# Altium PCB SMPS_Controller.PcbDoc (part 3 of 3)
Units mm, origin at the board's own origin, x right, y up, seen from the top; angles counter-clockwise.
Board outline 157 x 106 mm, 2 copper layers (Top Layer, Bottom Layer); 245 components, 175 nets, 948 pads, 171 vias.
Unrouted connection lines stored in the file: 2.
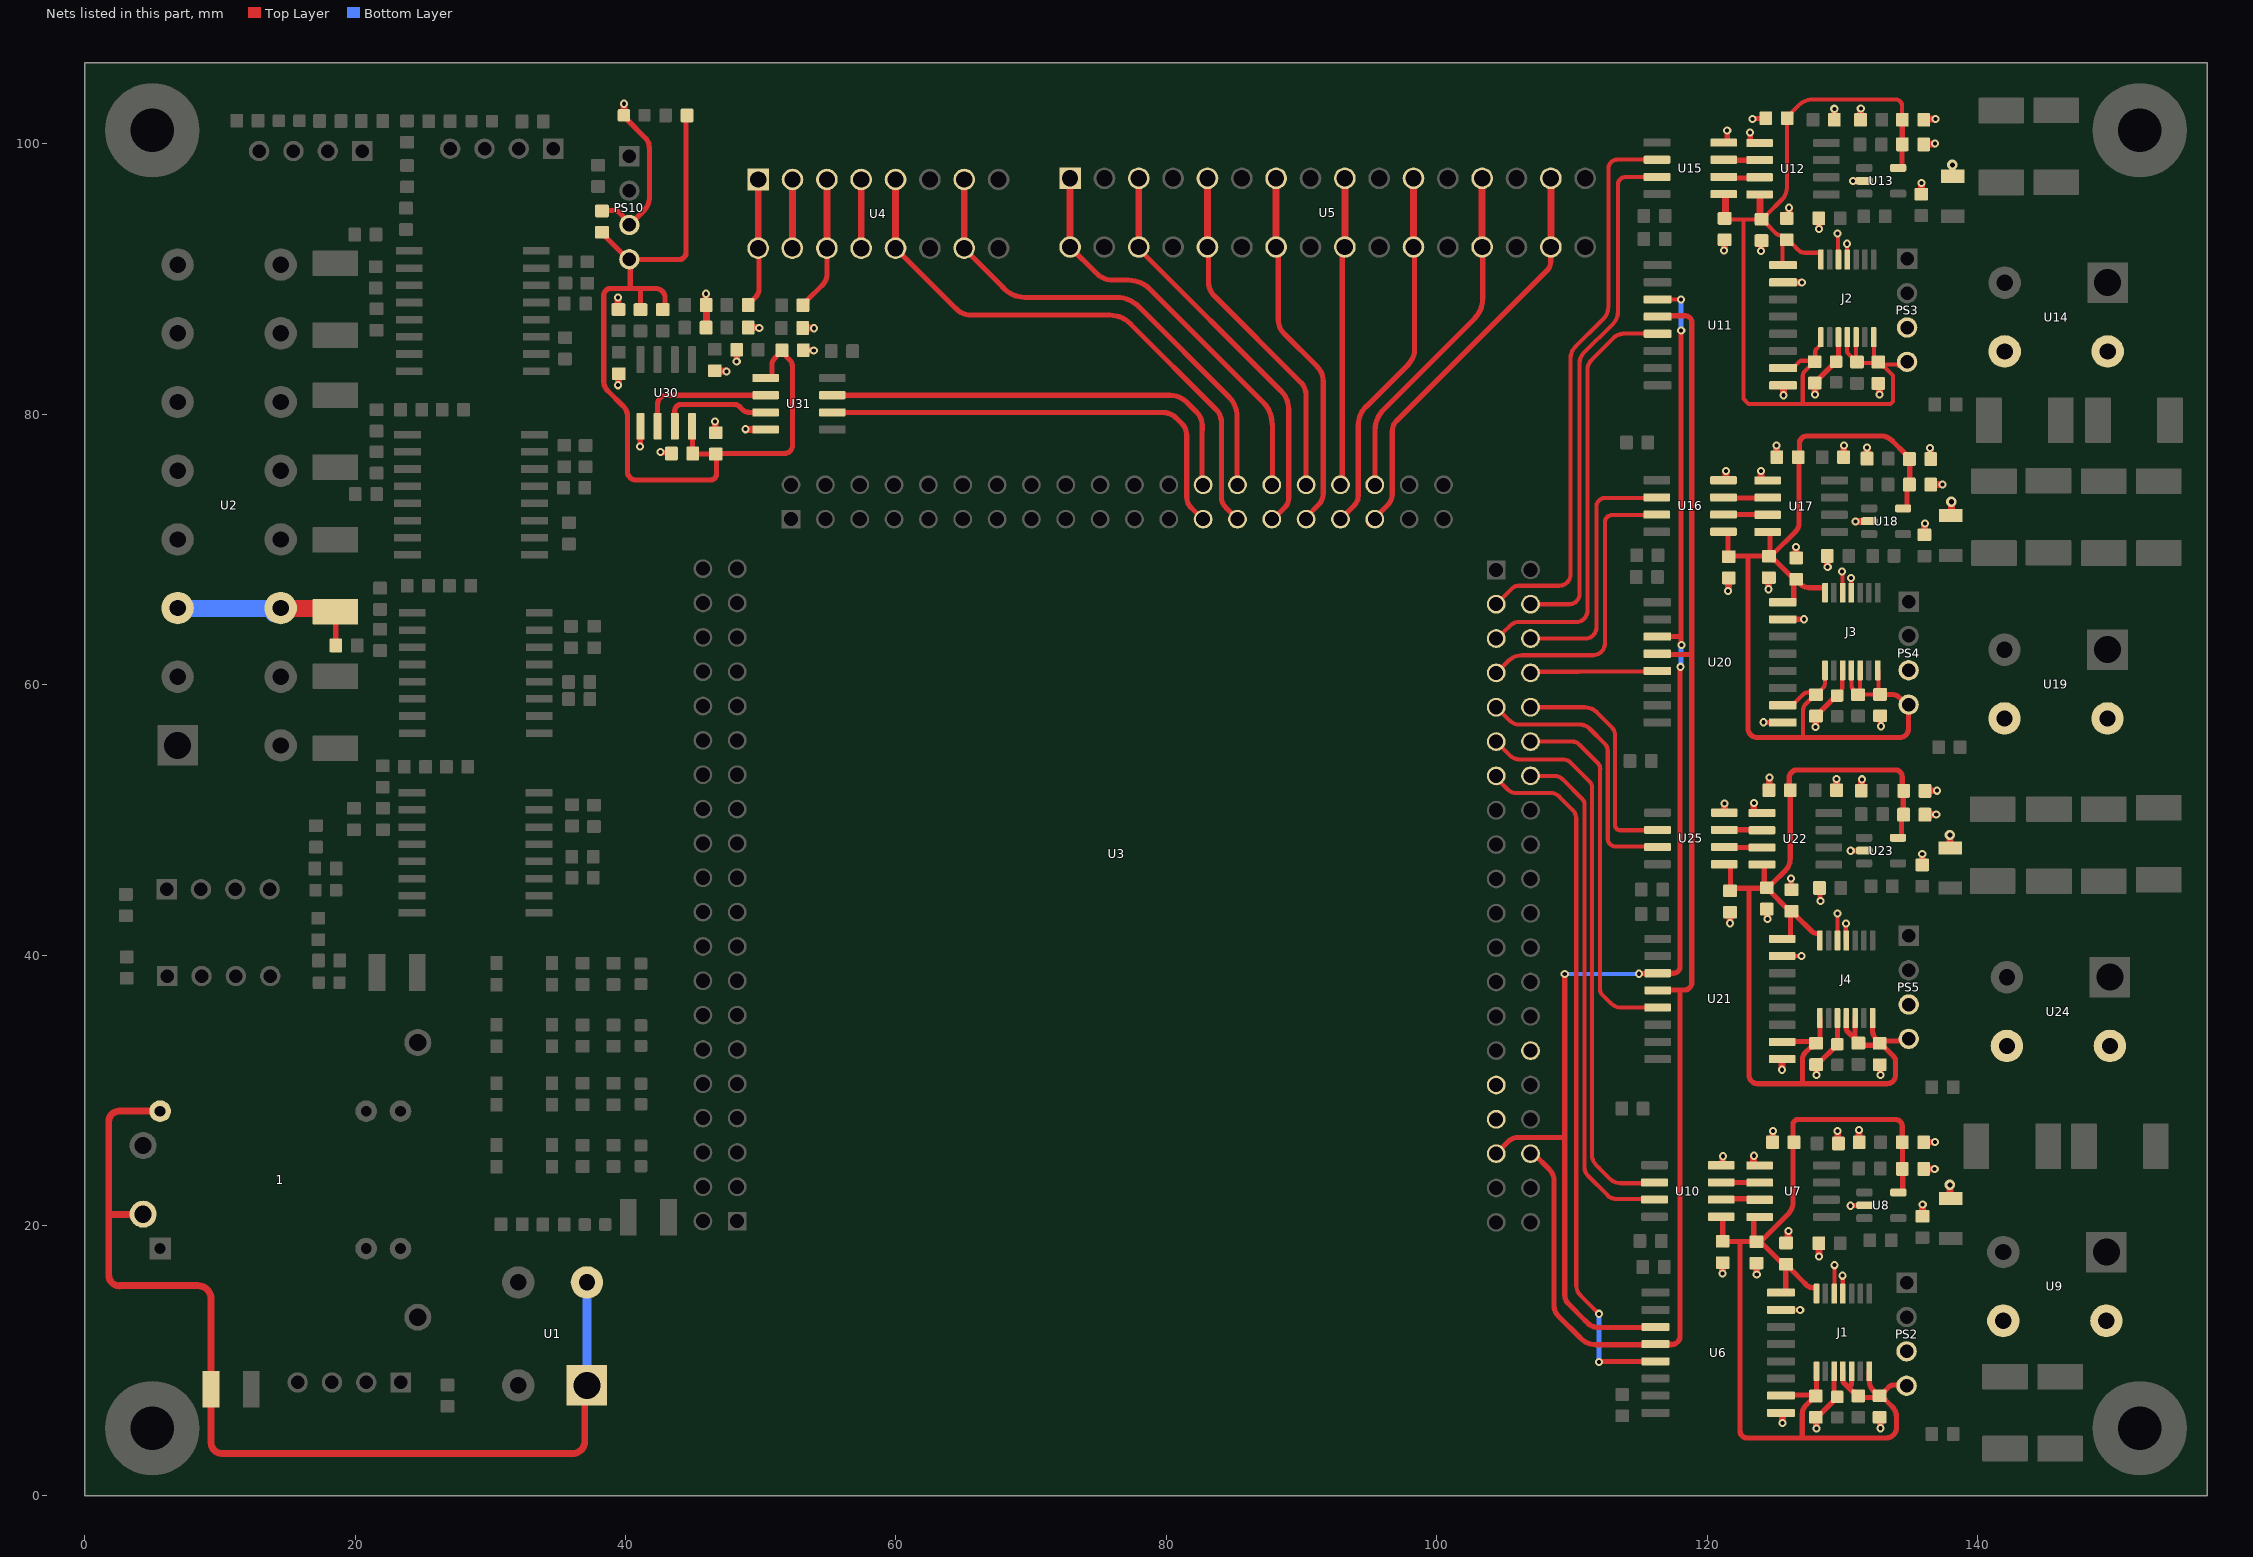
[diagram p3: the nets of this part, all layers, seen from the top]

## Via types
v1: diameter 0.6, hole 0.3, Top Layer to Bottom Layer, tented both sides, 163 vias
v2: diameter 0.762, hole 0.381, Top Layer to Bottom Layer, tented both sides, 8 vias

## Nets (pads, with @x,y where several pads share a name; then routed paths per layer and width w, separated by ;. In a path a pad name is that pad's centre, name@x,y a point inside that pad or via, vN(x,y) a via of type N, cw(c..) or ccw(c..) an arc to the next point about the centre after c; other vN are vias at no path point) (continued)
NetR67_1: R67.1 R68.1 U2.3 | length 13.3
  Top Layer w0.381: R68.1@18.567,62.904 R67.1@18.567,65.36
  Top Layer w1.27: U2.3@14.339,65.639 R67.1@17.673,65.639
  Bottom Layer w1.27: U2.3@6.719,65.639 13.817,65.639 13.97,65.487 U2.3@13.97,65.278
NetR70_1: R70.1 U4.1 | length 9.8
  Top Layer w0.381: R70.1@49.071,88.117 49.349,88.396 49.362,88.396 49.623,88.657 ccw(c48.994,89.286) 49.883,89.286 49.883,89.287 49.883,92.213 U4.1@49.815,92.281 ; U4.1@49.784,97.536 U4.1@49.815,97.505
  Top Layer w0.508: U4.1@49.815,92.281 U4.1@49.815,97.505
NetR71_1: R71.1 U4.3 | length 9.6
  Top Layer w0.381: R71.1@53.128,88.065 53.407,88.344 53.407,88.401 54.549,89.543 ccw(c53.674,90.419) 54.912,90.419 54.912,91.996 U4.3@55.044,92.128 ; U4.3@54.864,97.028 U4.3@54.895,96.997
  Top Layer w0.508: U4.3@54.895,92.281 U4.3@54.895,96.997
NetU3_B25: U3.B25 U31.6 | length 33.9
  Top Layer w0.381: U31.6@55.317,80.122 79.788,80.122 cw(c79.788,78.808) 80.717,79.737 ; 80.721,79.741 81.131,79.331 81.132,79.33 ccw(c81.4,79.6) 81.134,79.328 cw(c80.273,78.436) 81.513,78.437 81.513,78.435 81.513,73.846 ccw(c82.538,73.846) 81.813,73.12 ; 81.816,73.124 U3.B25@82.85,72.09
NetU3_B26: U3.B26 U31.7 | length 32.7
  Top Layer w0.381: U31.7@55.302,81.407 80.259,81.407 cw(c80.259,79.653) 81.499,80.893 ; 81.506,80.9 82.239,80.168 cw(c81.232,79.162) 82.656,79.162 82.656,78.845 ; U3.B26@82.653,74.994 82.653,78.845
NetU3_B27: U3.B27 U4.5 | length 42.6
  Top Layer w0.381: U4.5@59.944,97.282 U4.5@59.975,97.251 ; U4.5@59.975,92.281 64.45,87.807 64.451,87.805 ccw(c65.604,88.958) 65.604,87.328 65.605,87.328 75.823,87.328 75.826,87.328 cw(c75.825,85.185) 77.341,86.699 83.683,80.357 cw(c82.738,79.413) 84.074,79.413 84.074,73.907 ccw(c85.257,73.907) 84.42,73.071 84.447,73.045 ; 84.454,73.051 U3.B27@85.59,71.915
  Top Layer w0.508: U4.5@59.975,92.281 U4.5@59.975,97.251
NetU3_B28: U3.B28 U4.7 | length 35.3
  Top Layer w0.381: U4.7@65.024,97.028 U4.7@65.055,96.997 ; U4.7@65.055,92.252 67.845,89.462 67.859,89.448 ccw(c69.535,90.798) 69.535,88.646 69.536,88.646 76.302,88.646 76.305,88.646 cw(c76.304,86.31) 77.956,87.962 77.957,87.961 84.61,81.308 cw(c83.099,79.797) 85.235,79.797 ; U3.B28@85.238,74.805 85.238,79.797
  Top Layer w0.508: U4.7@65.055,92.281 U4.7@65.055,96.997
NetU3_B29: U3.B29 U5.3 | length 30.2
  Top Layer w0.381: U5.3@77.966,92.369 77.966,92.242 88.486,81.722 cw(c87.116,80.351) 89.054,80.351 89.054,73.793 cw(c88.104,73.793) 88.776,73.12 ; U3.B29@87.805,72.239 87.902,72.239 88.78,73.117
  Top Layer w0.508: U5.3@77.724,97.282 77.966,97.04 U5.3@77.966,92.369
NetU3_B30: U3.B30 U5.1 | length 30.2
  Top Layer w0.381: U5.1@72.886,92.369 74.818,90.437 74.819,90.436 ccw(c76.074,91.691) 76.074,89.916 76.076,89.916 77.203,89.916 cw(c77.203,87.697) 78.773,89.265 87.194,80.844 cw(c85.698,79.348) 87.814,79.348 87.814,79.264 ; U3.B30@87.846,74.858 87.846,79.264
  Top Layer w0.508: U5.1@72.39,97.282 72.507,97.282 72.886,96.903 U5.1@72.886,92.369
NetU3_B31: U3.B31 U5.7 | length 26.6
  Top Layer w0.381: U5.7@87.884,97.282 U5.7@88.126,97.04 ; U5.7@88.203,92.018 88.28,91.941 88.28,86.998 ccw(c89.742,86.998) 88.708,85.964 ; 88.715,85.971 91.163,83.522 ; U3.B31@90.424,72.136 90.424,72.457 91.279,73.312 ; 91.16,83.519 cw(c90.064,82.424) 91.614,82.424 91.614,74.139 cw(c90.452,74.139) 91.274,73.317
  Top Layer w0.508: U5.7@88.126,92.369 U5.7@88.126,97.04
NetU3_B32: U3.B32 U5.5 | length 25.4
  Top Layer w0.381: U5.5@82.804,97.536 U5.5@83.046,97.294 ; U5.5@83.123,92.018 83.123,89.797 83.123,89.796 ccw(c84.62,89.796) 83.562,88.738 83.563,88.736 89.984,82.315 89.985,82.314 cw(c89.165,81.493) 90.325,81.493 U3.B32@90.325,74.798
  Top Layer w0.508: U5.5@83.046,92.369 U5.5@83.046,97.294
NetU3_B33: U3.B33 U5.11 | length 26.9
  Top Layer w0.381: U3.B33@92.885,72.239 93.939,73.293 ; 93.93,73.302 ccw(c93.268,73.964) 94.205,73.964 94.205,79.213 cw(c96.096,79.213) 94.759,80.55 ; 94.766,80.542 97.946,83.722 ; 97.931,83.736 ccw(c96.888,84.779) 98.363,84.779 U5.11@98.363,92.018 ; U5.11@98.286,97.016 U5.11@98.552,97.282
  Top Layer w0.508: U5.11@98.286,92.369 U5.11@98.286,97.016
NetU3_B34: U3.B34 U5.9 | length 22.5
  Top Layer w0.381: U3.B34@92.885,74.779 93.012,74.906 93.012,92.155 U5.9@93.143,92.286 ; U5.9@93.206,97.27 U5.9@93.218,97.282
  Top Layer w0.508: U5.9@93.206,92.369 U5.9@93.206,97.27
NetU3_B35: U3.B35 U5.15 | length 30.9
  Top Layer w0.381: U3.B35@94.996,71.882 94.996,71.903 96.393,73.301 ccw(c95.612,74.081) 96.717,74.081 ; 96.71,74.081 96.71,78.734 cw(c97.796,78.734) 97.028,79.502 108.051,90.525 ; 108.06,90.516 108.164,90.621 ccw(c107.516,91.27) 108.433,91.27 U5.15@108.433,92.356 ; U5.15@108.204,97.282 U5.15@108.446,97.04
  Top Layer w0.508: U5.15@108.446,92.369 U5.15@108.446,97.04
NetU3_B36: U3.B36 U5.13 | length 25.6
  Top Layer w0.381: U3.B36@95.438,74.791 95.438,78.783 95.438,78.784 cw(c97.685,78.784) 96.096,80.374 102.811,87.089 ; 102.808,87.092 ccw(c101.352,88.548) 103.411,88.548 103.411,92.324 U5.13@103.366,92.369 ; U5.13@103.366,97.27 U5.13@103.378,97.282
  Top Layer w0.508: U5.13@103.366,92.369 U5.13@103.366,97.27
NetU3_C03: U3.C03 U15.6 | length 41.5
  Top Layer w0.305: U3.C03@104.4,65.984 cw(c104.598,65.752) 104.498,66.04 105.559,67.101 cw(c106.062,66.599) 106.062,67.31 109.043,67.31 ccw(c109.043,68.172) 109.905,68.172 109.905,84.146 ; 109.905,84.147 cw(c111.066,84.147) 110.246,84.969 112.155,86.878 112.324,87.047 ccw(c111.429,87.944) 112.696,87.944 112.696,98.153 cw(c113.375,98.153) 113.375,98.832 U15.6@116.287,98.832
NetU3_C04: U3.C04 U15.7 | length 38.5
  Top Layer w0.305: U3.C04@107.094,65.946 109.819,65.946 ccw(c109.819,66.694) 110.566,66.694 110.566,83.785 ; 110.566,83.787 cw(c111.595,83.787) 110.868,84.514 113.037,86.683 ccw(c112.148,87.574) 113.407,87.574 113.407,96.972 cw(c113.985,96.972) 113.985,97.55 U15.7@116.293,97.55
NetU3_C05: U3.C05 U11.5 | length 31.2
  Top Layer w0.305: 104.956,63.888 105.408,64.34 cw(c106.112,63.637) 106.112,64.632 ; 106.113,64.632 110.336,64.632 ccw(c110.336,65.44) 111.145,65.44 111.145,83.231 111.145,83.233 cw(c112.275,83.233) 111.476,84.033 113.077,85.643 cw(c113.293,85.428) 113.09,85.655 cw(c113.902,84.746) 113.091,85.656 cw(c113.902,84.746) 113.902,85.965 116.326,85.965 U11.5@116.342,85.949
NetU3_C06: U3.C06 U16.6 | length 19.1
  Top Layer w0.305: U3.C06@107.188,63.664 107.446,63.406 110.97,63.406 cw(c110.97,63.102) 110.978,63.406 ccw(c111.005,64.212) 111.811,64.212 ; 111.811,64.213 111.811,73.145 cw(c112.481,73.145) 112.481,73.815 U16.6@116.365,73.815
NetU3_C07: U3.C07 U16.7 | length 22.2
  Top Layer w0.305: U3.C07@104.427,60.866 105.325,61.764 cw(c106.31,60.78) 106.31,62.172 ; 106.312,62.172 111.564,62.172 ccw(c111.564,63.047) 112.439,63.047 112.439,71.99 cw(c112.994,71.99) 112.994,72.545 U16.7@116.365,72.545
NetU3_C08: U3.C08 U20.5 | length 9.4
  Top Layer w0.305: U3.C08@106.944,60.866 107.03,60.952 110.482,60.952 110.49,60.96 116.265,60.96 U20.5@116.32,61.014
NetU3_C09: U3.C09 U25.7 | length 20.3
  Top Layer w0.305: U3.C09@104.14,58.591 105.419,57.312 ; 105.428,57.322 ccw(c106.089,57.983) 106.089,57.048 110.57,57.048 cw(c110.569,55.985) 111.322,56.735 112.45,55.607 112.452,55.606 cw(c111.969,55.123) 112.652,55.123 112.652,55.121 112.652,48.606 ccw(c113.227,48.606) 113.227,48.031 115.998,48.031 U25.7@116.069,47.96
NetU3_C10: U3.C10 U25.6 | length 16.9
  Top Layer w0.305: U3.C10@106.964,58.307 106.984,58.326 110.939,58.326 cw(c110.939,57.038) 111.85,57.949 112.929,56.87 112.931,56.868 cw(c112.302,56.239) 113.192,56.24 113.192,56.238 113.192,49.612 ccw(c113.573,49.612) 113.573,49.23 U25.6@116.069,49.23
NetU3_C11: U3.C11 U10.6 | length 41.1
  Top Layer w0.305: U3.C11@104.648,55.626 104.648,55.543 105.429,54.762 105.43,54.761 ccw(c106.129,55.46) 106.129,54.471 106.131,54.471 109.286,54.471 cw(c109.286,53.534) 109.936,54.209 ; 109.937,54.209 cw(c109.725,53.989) 109.948,54.196 111.302,52.843 cw(c110.856,52.398) 111.486,52.398 111.486,25.242 ccw(c112.623,25.242) 111.819,24.439 111.986,24.272 ; 111.983,24.269 112.709,23.544 112.781,23.472 ccw(c113.636,24.327) 113.636,23.118 116.049,23.118 U10.6@116.11,23.179
NetU3_C12: U3.C12 U21.5 | length 26.5
  Top Layer w0.305: U3.C12@107.188,55.88 107.282,55.786 110.037,55.786 110.039,55.786 cw(c110.039,55.073) 110.543,55.577 ; 110.544,55.576 111.898,54.222 111.9,54.22 cw(c111.427,53.748) 112.092,53.673 112.092,37.421 ccw(c112.58,37.421) 112.236,37.074 112.828,36.482 112.835,36.489 112.891,36.434 112.908,36.417 ccw(c113.642,37.151) 113.642,36.113 U21.5@115.767,36.113
NetU3_C13: U3.C13 U6.5 | length 51.9
  Top Layer w0.305: U3.C13@104.404,53.246 104.404,53.098 105.24,52.262 ; 105.236,52.258 ccw(c105.899,52.921) 105.899,51.984 108.412,51.984 cw(c108.412,51.023) 109.091,51.702 ; 109.086,51.696 110.078,50.704 ; 110.079,50.703 cw(c109.498,50.121) 110.321,50.121 110.321,15.569 ccw(c111.328,15.569) 110.616,14.857 ; 110.618,14.858 v1(112.014,13.462)
  Top Layer w0.381: v1(112.014,9.906) 112.034,9.926 U6.5@115.645,9.926
  Bottom Layer w0.381: v1(112.014,9.906) v1(112.014,13.462)
NetU3_C14: U3.C14 U10.7 | length 38.1
  Top Layer w0.305: U3.C14@106.944,53.246 108.722,53.246 cw(c108.722,52.431) 109.298,53.008 109.299,53.007 110.767,51.539 cw(c110.335,51.107) 110.946,51.107 110.946,24.239 ccw(c111.696,24.239) 111.166,23.709 112.631,22.243 ; 112.621,22.234 ccw(c113.278,22.891) 113.278,21.962 U10.7@116.13,21.962
NetU3_C30: U3.C30
NetU3_C31: U3.C31
NetU3_C33: U3.C33
NetU3_C34: 
NetU3_C35: U3.C35 U6.3 U11.3 U20.3 U21.3 | length 98.3
  Top Layer w0.305: U11.3@116.342,88.489 v1(118.059,88.489)
  Top Layer w0.381: U3.C35@104.404,25.306 105.298,26.2 cw(c106.045,25.454) 106.045,26.511 109.474,26.511 ; v1(109.474,38.608) 109.474,26.511 ; 109.697,14.257 cw(c109.413,14.003) 109.725,14.221 110.995,12.951 ; 109.696,14.257 cw(c110.341,14.837) 109.474,14.837 109.474,26.511 ; 110.998,12.954 111.192,12.76 ccw(c111.95,13.517) 111.95,12.446 U6.3@115.622,12.446 ; v1(114.958,38.615) 114.977,38.634 116.326,38.634 U21.3@116.345,38.653 117.505,38.653 ccw(c117.505,39.154) 118.007,39.154 118.007,61.278 v1(118.046,61.318) ; U6.3@116.152,12.607 U6.3@116.194,12.564 ; U20.3@116.335,63.57 117.967,63.57 118.025,63.511 ; v1@118.063,62.965 118.063,86.157 v1(118.086,86.18) ; v1@118.09,62.938 v1(118.101,62.927)
  Bottom Layer w0.305: v1(109.474,38.608) 114.951,38.608 v1(114.958,38.615)
  Bottom Layer w0.381: v1(118.046,61.318) 118.074,61.346 118.074,62.9 v1(118.101,62.927) ; v1(118.059,88.489) 118.073,88.476 118.073,86.194 v1(118.086,86.18)
NetU3_C36: U3.C36 U6.4 U11.4 U20.4 U21.4 | length 104.6
  Top Layer w0.381: U3.C36@106.944,25.306 107.18,25.306 108.31,24.177 ; 108.31,24.177 cw(c107.418,23.285) 108.68,23.285 108.68,14.083 108.68,14.081 ccw(c109.807,14.081) 109.011,13.283 110.629,11.665 110.63,11.664 ccw(c111.808,12.841) 111.808,11.176 111.809,11.176 U6.4@115.384,11.176 ; U6.4@116.184,11.217 117.348,11.217 ; U20.4@116.32,62.284 116.374,62.23 118.872,62.23 ; U11.4@116.342,87.219 116.402,87.279 118.389,87.279 cw(c118.389,86.796) 118.872,86.796 118.872,62.23 ; U21.4@116.371,37.408 118.32,37.408 ccw(c118.32,37.96) 118.872,37.96 118.872,62.23 ; 117.348,11.176 ccw(c117.348,11.838) 118.01,11.838 118.01,37.111
NetU7_6: U7.6 U10.3 | length 2.9
  Top Layer w0.381: U10.3@121.083,23.175 U7.6@123.984,23.175
NetU7_7: U7.7 U10.2 | length 2.9
  Top Layer w0.381: U10.2@120.988,21.97 123.866,21.97 U7.7@123.893,21.943
NetU12_6: U12.6 U15.3 | length 3.4
  Top Layer w0.381: U15.3@120.776,98.787 U12.6@124.172,98.787
NetU12_7: U12.7 U15.2 | length 3.1
  Top Layer w0.381: U15.2@121.043,97.483 U12.7@124.124,97.483
NetU16_2: U16.2 U17.7 | length 3.2
  Top Layer w0.381: U16.2@121.221,72.578 U17.7@124.466,72.578
NetU16_3: U16.3 U17.6 | length 3.3
  Top Layer w0.381: U16.3@121.219,73.846 121.253,73.812 U17.6@124.483,73.812
NetU22_6: U22.6 U25.3 | length 2.7
  Top Layer w0.381: U25.3@120.748,49.266 U22.6@123.456,49.266
NetU22_7: U22.7 U25.2 | length 2
  Top Layer w0.381: U25.2@121.574,47.962 123.481,47.962 U22.7@123.553,47.889
NetU30_6: U30.6 U31.2 | length 9.3
  Top Layer w0.381: U30.6@42.379,79.795 42.379,80.733 cw(c43.053,80.733) 43.053,81.407 U31.2@50.362,81.407
NetU30_7: U30.7 U31.3 | length 8.3
  Top Layer w0.381: U30.7@43.649,79.106 43.649,80.259 cw(c44.113,80.259) 44.113,80.723 ; 44.113,80.72 48.09,80.72 cw(c48.09,80.329) 48.267,80.678 cw(c48.094,80.338) 48.271,80.675 cw(c47.798,79.773) 48.619,80.377 ccw(c48.924,80.604) 48.673,80.317 ccw(c49.155,80.871) 48.675,80.316 ccw(c49.155,80.871) 49.155,80.137 U31.3@50.362,80.137
SIG_5V: C89.1 C90.1 C96.2 C98.2 PS10.4 R74.1 R76.1 R78.2 U30.8 U31.1 | length 68.3
  Top Layer w0.381: C98.2@38.18,93.473 38.183,93.473 38.462,93.194 38.462,93.191 40.196,91.457 PS10.4@40.288,91.457 40.349,91.396 40.349,89.301 ; 38.65,81.778 cw(c39.276,82.404) 38.391,82.404 38.391,88.785 cw(c38.906,88.785) 38.906,89.301 40.349,89.301 ; 38.651,81.78 39.857,80.574 39.858,80.573 cw(c39.184,79.899) 40.137,79.899 40.137,79.897 40.137,75.774 ccw(c40.778,75.774) 40.778,75.133 46.272,75.133 ccw(c46.272,75.597) 46.736,75.597 C90.1@46.736,77.086 ; PS10.4@40.386,91.44 43.958,91.44 ccw(c43.958,91.96) 44.478,91.96 R78.2@44.478,102.108 ; 41.1,89.301 42.23,89.301 cw(c42.23,88.605) 42.926,88.605 42.926,88.018 R74.1@42.672,87.63 ; R76.1@41.111,87.738 41.111,89.191 41.001,89.301 40.349,89.301 ; C89.1@44.958,77.095 U30.8@44.958,78.232 ; C89.1@44.978,77.095 45.019,77.054 C90.1@46.586,77.054 ; C90.1@46.682,77.055 46.728,77.102 51.77,77.102 ccw(c51.77,77.686) 52.354,77.686 52.354,83.523 ; U31.1@50.362,82.677 50.727,82.677 50.836,82.786 50.836,83.665 cw(c51.472,83.665) 51.022,84.115 ; 51.012,84.126 51.301,84.415 51.749,84.415 52.136,84.028 cw(c51.631,83.523) 52.345,83.523
SIG_GND: C89.2 C90.2 C91.1 C92.1 C93.2 C94.2 C96.1 C98.1 D14.C PS10.3 R72.2 R73.2 R75.2 R77.2 U4.2 U4.4 U30.5 U31.4 | length 36.6
  Top Layer w0.381: C98.1@38.16,95.071 39.137,95.071 cw(c39.137,94.442) 39.582,94.887 ; R77.2@39.461,87.766 R77.2@39.478,87.748 ; 39.579,94.884 40.288,94.175 PS10.3@40.288,93.997 41.435,95.145 ; D14.C@39.871,102.117 40.144,101.843 40.144,101.755 41.499,100.401 cw(c40.869,99.771) 41.76,99.771 ; v1@41.086,77.649 U30.5@41.086,79.084 ; 41.428,95.151 ccw(c40.617,95.963) 41.765,95.963 41.765,99.771 ; v1(42.576,77.197) 42.618,77.155 43.339,77.155 C89.2@43.398,77.095 ; R75.2@45.96,86.406 R75.2@46.003,86.45 ; C93.2@45.969,88.077 C93.2@46.003,88.042 ; C90.2@46.682,78.635 C90.2@46.719,78.598 ; v1(48.878,78.892) v1@48.891,78.879 ; U31.4@50.35,78.879 U31.4@50.362,78.867
  Top Layer w0.508: R77.2@39.453,87.774 v1(39.453,88.625) ; v1(39.457,82.145) 39.475,82.163 39.475,82.966 C94.2@39.509,83 ; D14.C@39.871,102.117 39.881,102.127 v1@39.881,102.966 ; C93.2@45.952,88.137 v1(45.952,88.911) ; R75.2@46.003,86.45 C93.2@46.003,88.042 ; C91.1@46.606,83.22 46.643,83.183 47.443,83.183 v1(47.461,83.166) ; v1(46.621,79.467) 46.638,79.45 46.638,78.679 C90.2@46.719,78.598 ; v1(48.227,83.896) C92.1@48.227,84.764 ; v1@48.891,78.879 U31.4@50.35,78.879 ; R72.2@49.078,86.417 49.091,86.403 49.882,86.403 v1(49.895,86.39) ; U4.2@52.335,92.281 52.345,92.291 52.345,97.049 U4.2@52.578,97.282 ; R73.2@53.119,86.369 53.937,86.369 v1(53.945,86.36) ; C96.1@53.174,84.713 53.19,84.729 53.916,84.729 v1(53.923,84.721) ; U4.4@57.435,92.281 57.435,97.313 U4.4@57.658,97.536
  Top Layer w0.635: R73.2@53.086,86.184 R73.2@53.127,86.184
  other v1: 41.082,77.604 39.881,102.966
VCC_9-36V: 1.16 1.200 C3.2 U1.1 | length 76.8
  Top Layer w0.508: 2.582,15.526 cw(c2.582,16.33) 1.778,16.33 1.778,20.81 ; 2.582,15.541 8.376,15.541 cw(c8.376,14.569) 9.348,14.569 9.348,14.423 ; 1.200@4.3,20.81 1.778,20.81 ; 1.16@5.578,28.448 2.54,28.448 ccw(c2.54,27.686) 1.778,27.686 1.778,20.81 ; C3.2@9.347,7.163 9.347,3.925 ccw(c10.14,3.925) 10.14,3.132 36.103,3.132 ; C3.2@9.347,7.882 9.347,14.423 ; 36.103,3.131 ccw(c36.103,4.012) 36.984,4.012 36.984,8.002 U1.1@37.15,8.168
  Bottom Layer w0.635: U1.1@37.15,8.168 37.15,15.306 U1.1@37.338,15.494
VLT1_5V: C20.2 C21.2 C22.1 C23.1 C24.1 C25.1 C30.2 C32.2 J2.7 J2.8 J2.11 J2.12 J2.14 PS3.4 R27.2 U11.10 U11.16 U12.8 U13.5 U15.1 | length 79.6
  Top Layer w0.305: U15.1@121.236,96.283 U15.1@121.376,96.143 ; C25.1@121.376,94.414 122.698,94.414 ; U12.8@123.487,96.216 123.799,96.216 U12.8@123.905,96.11 ; C20.2@123.635,94.414 122.698,94.414 ; C20.2@123.889,94.387 124.108,94.387 124.391,94.104 124.391,94.086 125.106,93.371 ccw(c125.476,93.742) C23.1@125.476,93.218 ; C20.2@123.905,94.547 124.199,94.547 124.408,94.757 124.418,94.757 125.563,95.901 ccw(c124.741,96.723) 125.904,96.723 125.904,101.87 C32.2@125.929,101.895 ; C20.2@124.033,94.422 C20.2@124.141,94.529 ; C23.1@125.574,92.583 125.574,91.077 U11.16@125.622,91.029 ; C23.1@125.897,92.902 126.215,92.584 126.307,92.584 126.744,92.148 ccw(c127.231,92.632) 127.231,91.945 ; C32.2@125.978,101.985 126.247,102.253 126.247,102.31 126.8,102.864 cw(c127.833,101.832) 127.833,103.292 133.914,103.292 cw(c133.914,102.785) 134.421,102.785 C24.1@134.421,101.801 ; U11.10@126.492,83.566 126.799,83.873 ; 126.8,83.872 cw(c127.001,83.67) 127.001,83.955 127.886,83.955 C30.2@127.96,83.882 ; 127.232,91.945 128.368,91.945 128.42,91.893 J2.7@128.42,91.438 ; J2.8@128.42,85.698 128.368,85.115 128.08,84.828 ccw(c128.264,84.644) 128.004,84.645 128.004,83.966 127.602,83.564 127.602,83.555 127.209,83.162 ccw(c127.53,82.841) 127.076,82.841 127.076,80.763 ; J2.11@130.36,85.687 130.36,84.707 ccw(c130.724,84.707) 130.466,84.45 ; 130.468,84.452 130.732,84.188 130.732,84.176 131.009,83.9 131.02,83.9 J2.12@131.02,85.698 ; R27.2@131.044,83.806 131.068,83.782 C21.2@132.425,83.782 ; C21.2@132.334,83.892 J2.14@132.334,85.684 ; C21.2@132.453,83.877 C21.2@132.645,83.877 ; C21.2@132.663,83.859 132.831,83.859 132.831,83.731 133.021,83.541 133.021,83.685 134.048,83.685 PS3.4@134.164,83.569 ; C21.2@133.096,83.538 133.761,82.874 133.761,80.941 133.582,80.763 127.076,80.763 ; C22.1@134.341,99.852 C22.1@134.5,100.012 ; 122.698,94.414 122.698,81.496 122.694,81.492 122.694,81.421 122.694,81.149 122.887,80.956 123.08,80.763 123.352,80.763 123.354,80.763 127.076,80.763
  Top Layer w0.381: U13.5@134.13,98.217 134.308,98.217 134.413,98.322 134.413,99.924 C22.1@134.448,99.959 ; C22.1@134.434,99.972 C24.1@134.434,101.788
  Top Layer w0.508: C25.1@121.376,94.414 U15.1@121.376,96.143 ; C20.2@123.905,94.547 U12.8@123.905,96.11
VLT1_GND: C20.1 C21.1 C22.2 C23.2 C24.2 C25.2 C26.2 C27.2 C28.2 C30.1 C32.1 D7.C J2.4 J2.5 J2.10 PS3.3 R23.1 R26.2 U11.9 U11.15 U12.5 U13.2 U14.2 U15.4 | length 23
  Top Layer w0.305: v1(129.656,93.374) 129.688,93.342 129.688,91.47 J2.5@129.72,91.438 ; v1(130.353,92.609) 130.361,92.6 130.361,91.447 J2.4@130.37,91.438
  Top Layer w0.381: U15.4@121.236,100.093 121.38,100.093 121.49,100.203 v1(121.49,100.979) ; v1(123.19,100.838) 123.19,100.177 123.299,100.068 U12.5@123.886,100.068 ; v1(123.358,101.848) 123.382,101.872 124.325,101.872 C32.1@124.349,101.895 ; U11.9@125.622,82.139 U11.9@125.65,82.111 ; C30.1@127.96,82.302 C30.1@127.971,82.29 ; v1@127.971,81.462 v1(127.982,81.45) ; C30.1@128.27,82.296 128.279,82.305 128.279,82.635 D7.C@129.207,83.563 ; D7.C@129.397,83.789 D7.C@129.466,83.789 ; D7.C@129.72,84.148 J2.10@129.72,85.698
  Top Layer w0.508: v1(121.259,92.1) 121.276,92.117 121.276,92.882 C25.2@121.296,92.902 ; v1(123.989,92.069) 124.006,92.086 124.006,92.815 C20.1@124.033,92.842 ; U11.15@125.622,89.759 125.626,89.755 127.004,89.755 v1(127.007,89.751) ; v1(125.65,81.405) U11.9@125.65,82.111 ; C23.2@125.897,94.482 126.05,94.635 126.05,95.253 v1(126.067,95.27) ; v1@127.971,81.462 C30.1@127.971,82.29 ; C28.2@128.262,94.476 128.272,94.466 128.272,93.71 v1(128.283,93.7) ; v1(129.411,102.591) 129.414,102.588 129.414,101.778 C27.2@129.417,101.775 ; v1(130.787,97.239) 130.801,97.253 131.606,97.253 U13.2@131.62,97.267 ; R26.2@131.351,101.775 131.361,101.785 131.361,102.615 v1(131.371,102.625) ; C21.1@132.663,82.279 132.747,82.194 132.747,81.468 v1(132.765,81.45) ; C26.2@135.846,96.272 135.851,96.277 135.851,97.103 v1(135.856,97.108) ; C22.2@136.028,99.959 136.207,99.959 136.244,99.995 136.839,99.995 v1(136.856,100.013) ; C24.2@136.028,101.775 136.192,101.775 136.244,101.826 136.866,101.826 v1(136.884,101.844) ; v2(138.145,98.446) 138.145,97.643 R23.1@138.186,97.602
VLT2_5V: C34.2 C35.2 C36.1 C37.1 C38.1 C39.1 C44.2 C46.2 J3.7 J3.8 J3.11 J3.12 J3.14 PS4.4 R36.2 U16.1 U17.8 U18.5 U20.10 U20.16 | length 78
  Top Layer w0.305: U20.10@125.6,58.474 126.477,58.622 126.477,58.633 127.097,59.253 cw(c127.533,58.817) 127.533,59.434 127.693,59.434 128.067,59.27 127.693,58.953 127.684,58.953 127.279,58.547 ccw(c127.702,58.124) 127.104,58.124 127.104,56.082 ; C46.2@128.27,59.436 128.272,59.436 128.581,59.745 ; 128.576,59.749 ccw(c128.218,60.107) 128.725,60.107 J3.8@128.725,61.057 ; J3.11@130.703,60.587 130.675,60.559 130.675,60.004 ccw(c131.294,60.004) R36.2@130.856,59.566 ; R36.2@131.174,59.256 131.183,59.266 132.758,59.266 C35.2@132.842,59.182 ; R36.2@131.32,59.403 J3.12@131.32,61.053 ; C35.2@132.588,59.436 132.677,59.525 132.677,61.005 J3.14@132.625,61.057
  Top Layer w0.381: U16.1@121.219,71.306 121.438,71.306 121.548,71.197 121.548,69.526 C34.2@121.606,69.467 ; C34.2@121.821,69.62 121.961,69.48 121.983,69.501 123.03,69.501 ; C39.1@124.301,69.501 123.03,69.501 ; U17.8@124.489,71.179 124.546,71.179 124.655,71.07 C39.1@124.655,69.836 ; C39.1@124.714,69.383 124.882,69.215 125.004,69.215 126.148,68.071 126.311,68.071 C44.2@126.591,67.791 126.416,67.617 126.416,66.204 126.307,66.094 U20.16@125.6,66.094 ; C39.1@124.861,69.64 126.554,71.333 ccw(c125.939,71.949) 126.809,71.949 126.809,71.95 126.809,76.502 C37.1@126.743,76.822 126.83,77.141 126.83,77.818 cw(c127.403,77.818) 127.403,78.391 132.848,78.391 cw(c132.848,77.187) 133.699,78.038 134.688,77.05 134.688,76.962 C36.1@134.967,76.682 ; C44.2@126.886,67.45 ccw(c127.573,68.137) 127.573,67.165 128.71,67.165 128.725,67.151 J3.7@128.725,66.797 ; J3.12@131.325,60.675 J3.12@131.325,61.057 ; C35.2@132.796,59.275 133.63,59.275 cw(c133.63,58.361) 134.276,59.007 ; C36.1@134.688,76.609 C36.1@134.971,76.326 ; U18.5@134.783,73.024 134.783,74.386 C38.1@134.991,74.595 ; PS4.4@134.887,57.881 134.887,56.714 cw(c134.256,56.714) 134.256,56.082 127.104,56.082 123.724,56.082 cw(c123.724,56.776) 123.03,56.776 123.03,69.501 ; C38.1@134.988,74.727 C36.1@134.988,76.309
VLT2_GND: C34.1 C35.1 C36.2 C37.2 C38.2 C39.2 C40.2 C41.1 C42.1 C44.1 C46.1 D8.C J3.4 J3.5 J3.10 PS4.3 R32.1 R35.2 U16.4 U17.5 U18.2 U19.2 U20.9 U20.15 | length 23.2
  Top Layer w0.305: D8.C@129.308,58.884 129.604,59.18 D8.C@129.614,59.18 ; D8.C@129.831,59.425 ccw(c129.418,59.838) 130.002,59.838 130.002,61.035 J3.10@130.025,61.057 ; v1(129.994,68.371) 130.01,68.356 130.01,66.813 J3.5@130.025,66.797 ; v1(130.651,67.9) 130.663,67.888 130.663,66.83 J3.4@130.674,66.818
  Top Layer w0.381: C34.1@121.598,67.879 C34.1@121.606,67.887 ; v1(124.177,57.216) 124.183,57.21 125.594,57.21 U20.9@125.6,57.204 ; U20.15@125.6,64.824 125.605,64.83 127.174,64.83 v1(127.18,64.836) ; C46.1@128.392,58.012 129.286,58.906 D8.C@129.286,58.928
  Top Layer w0.508: U16.4@121.219,75.116 121.363,75.116 121.409,75.162 v1(121.409,75.809) ; v1(121.556,66.917) 121.573,66.935 121.573,67.854 C34.1@121.598,67.879 ; v1(123.985,75.809) 123.985,75.147 124.031,75.101 U17.5@124.483,75.101 ; v1(124.53,67.052) 124.548,67.069 124.548,67.891 C39.2@124.572,67.915 ; v1(125.131,77.684) 125.147,77.668 125.147,76.838 C37.2@125.163,76.822 ; v1(126.581,70.185) 126.586,70.18 126.586,69.376 C44.1@126.591,69.371 ; v1(128.019,56.861) 128.035,56.877 128.035,57.656 C46.1@128.051,57.672 ; C42.1@128.894,69.523 128.909,69.509 128.909,68.706 v1(128.923,68.692) ; C41.1@130.094,76.822 130.106,76.834 130.106,77.662 v1(130.117,77.673) ; v1(130.979,72.06) 130.992,72.072 131.683,72.072 U18.2@131.718,72.108 ; R35.2@131.832,76.715 131.838,76.72 131.838,77.542 v1(131.843,77.548) ; C35.1@132.796,57.695 132.843,57.647 132.843,56.937 v1(132.861,56.92) ; C40.2@136.075,71.082 136.091,71.098 136.091,71.909 v1(136.107,71.924) ; v1(136.501,77.504) 136.518,77.486 136.518,76.711 C36.2@136.547,76.682 ; C38.2@136.547,74.794 136.549,74.796 137.399,74.796 v1(137.401,74.797) ; R32.1@138.022,72.497 138.072,72.547 v2(138.072,73.525)
VLT3_5V: C48.2 C49.2 C50.1 C51.1 C52.1 C53.1 C58.2 C60.2 J4.7 J4.8 J4.11 J4.12 J4.14 PS5.4 R45.2 U21.10 U21.16 U22.8 U23.5 U25.1 | length 81
  Top Layer w0.381: U25.1@121.278,46.714 121.622,46.714 121.732,46.604 121.732,44.776 C48.2@121.702,44.746 ; C48.2@121.941,44.934 123.094,44.934 ; U22.8@123.952,46.736 124.077,46.736 124.235,46.578 C60.2@124.235,44.975 ; C60.2@124.23,44.934 123.094,44.934 ; C60.2@124.42,44.937 124.498,44.937 124.74,44.696 124.74,44.618 125.834,43.524 125.964,43.524 C53.1@126.244,43.244 ; C60.2@124.728,45.193 125.793,46.258 ccw(c124.925,47.128) 126.153,47.157 cw(c126.534,47.164) 126.153,47.162 126.153,47.164 C51.1@126.153,52.183 ; U21.10@125.555,33.573 125.583,33.601 127.75,33.601 127.788,33.562 127.788,33.217 127.75,33.179 127.662,33.179 127.252,32.768 ; C51.1@126.076,52.072 126.076,53.099 cw(c126.666,53.099) 126.666,53.689 133.92,53.689 cw(c133.92,53.172) 134.438,53.172 134.438,52.46 C52.1@134.545,52.189 ; U21.16@126.168,41.237 126.168,43.123 126.287,43.241 126.563,42.965 126.563,42.927 127.723,41.768 ccw(c128.163,42.208) J4.7@128.163,41.585 ; 127.254,32.766 ccw(c127.74,32.28) 127.053,32.28 127.053,30.48 ; C49.2@128.07,33.458 128.35,33.738 J4.8@128.35,35.329 ; J4.11@130.296,35.332 130.296,34.584 ccw(c130.718,34.584) 130.42,34.286 ; 130.43,34.296 130.964,33.762 130.964,33.753 R45.2@130.974,33.753 ; R45.2@130.857,33.825 R45.2@131.197,33.486 R45.2@131.348,33.335 ; R45.2@130.944,33.812 J4.12@130.944,35.33 ; R45.2@131.435,33.322 C58.2@132.452,33.322 ; J4.14@132.246,35.332 132.246,34.403 ccw(c133.166,34.403) C58.2@132.516,33.752 ; C58.2@132.53,33.472 C58.2@132.53,33.677 ; C58.2@132.757,33.53 133.095,33.192 133.101,33.192 133.807,32.487 cw(c133.481,32.16) 133.942,32.16 133.942,31.102 cw(c133.32,31.102) 133.32,30.48 127.053,30.48 ; C58.2@132.775,33.472 132.943,33.64 134.761,33.64 PS5.4@134.918,33.796 ; U23.5@134.004,48.618 134.268,48.618 134.372,48.722 134.372,50.072 C50.1@134.461,50.161 ; C50.1@134.509,50.314 C52.1@134.509,51.904 ; 123.094,44.934 123.094,31.131 ccw(c123.746,31.131) 123.746,30.48 127.053,30.48
VLT3_GND: C48.1 C49.1 C50.2 C51.2 C52.2 C53.2 C54.2 C55.2 C56.2 C58.1 C60.1 D9.C J4.4 J4.5 J4.10 PS5.3 R41.1 R44.2 U21.9 U21.15 U22.5 U23.2 U24.2 U25.4 | length 24
  Top Layer w0.305: U21.15@125.555,39.923 125.56,39.918 126.977,39.918 v1(126.982,39.913) ; v1(129.639,43.057) 129.643,43.053 129.643,41.076 J4.5@129.646,41.072 ; v1@130.257,42.3 130.257,41.112 J4.4@130.296,41.072
  Top Layer w0.381: U25.4@121.256,50.517 U25.4@121.294,50.555 ; U22.5@123.368,50.607 123.477,50.498 U22.5@124.062,50.498 ; C51.2@124.371,52.398 C51.2@124.58,52.189 ; v1(126.212,45.655) 126.228,45.639 126.228,44.84 C53.2@126.244,44.824 ; C49.1@128.149,31.918 128.389,32.158 128.41,32.158 129.38,33.128 129.38,33.179 129.644,33.443 D9.C@129.654,33.443 ; C56.2@128.315,44.961 128.349,44.927 128.349,44.027 v1(128.383,43.993) ; C55.2@129.54,52.226 C55.2@129.576,52.189 ; D9.C@129.649,33.484 J4.10@129.649,35.329 ; v1(130.624,47.71) 130.63,47.716 131.609,47.716 U23.2@131.614,47.721 ; R44.2@131.404,52.165 R44.2@131.412,52.157 ; C52.2@136.118,52.141 C52.2@136.141,52.163
  Top Layer w0.508: U25.4@121.294,50.555 v1(121.294,51.209) ; v1(121.695,42.347) 121.698,42.351 121.698,43.163 C48.1@121.702,43.166 ; U22.5@123.368,50.607 123.457,50.697 123.457,51.224 v1(123.475,51.241) ; C51.2@124.371,52.398 124.55,52.398 124.597,52.445 124.597,53.107 v1(124.615,53.125) ; C60.1@124.42,43.395 124.45,43.365 124.45,42.667 v1(124.468,42.65) ; v1(125.555,31.511) U21.9@125.555,32.303 ; C49.1@128.066,31.893 128.085,31.875 128.085,31.155 v1(128.102,31.138) ; C55.2@129.54,52.226 129.581,52.267 129.581,53.012 v1(129.586,53.017) ; R44.2@131.404,52.165 131.433,52.194 131.433,52.98 v1(131.45,52.998) ; C58.1@132.8,31.867 132.805,31.862 132.805,31.14 v1(132.823,31.123) ; C54.2@135.915,46.663 v1(135.916,47.474) ; C50.2@136.117,50.383 136.123,50.39 136.945,50.39 v1(136.952,50.396) ; C52.2@136.141,52.163 136.157,52.147 137.004,52.147 v1(137.01,52.153) ; v2(137.96,48.879) 137.96,48.003 R41.1@138.012,47.951
  other v1: 130.274,42.317
VLT4_5V: C6.2 C7.2 C8.1 C9.1 C10.1 C11.1 C16.2 C18.2 J1.7 J1.8 J1.11 J1.12 J1.14 PS2.4 R18.2 U6.10 U6.16 U7.8 U8.5 U10.1 | length 84.1
  Top Layer w0.305: 121.666,18.796 121.691,18.821
  Top Layer w0.381: U10.1@121.05,20.639 121.155,20.534 C8.1@121.155,18.821 C8.1@121.434,18.542 ; 121.691,18.821 122.444,18.821 ; C6.2@123.451,18.821 cw(c123.451,17.672) 124.263,18.485 C11.1@125.476,17.272 ; 123.452,19.272 123.452,20.515 123.478,20.54 U7.8@123.543,20.475 ; U7.8@123.562,20.624 U7.8@123.89,20.624 ; U6.10@125.464,7.407 125.526,7.468 127.983,7.468 127.733,7.101 127.29,6.657 ccw(c127.893,6.054) 127.04,6.054 127.04,6.052 127.04,4.287 ; U6.16@125.464,15.027 125.706,15.027 125.816,15.136 C11.1@125.816,17.096 ; C11.1@125.842,17.108 125.897,17.108 126.162,16.843 126.162,16.788 127.269,15.681 ; 125.984,20.828 ccw(c125.077,21.735) 126.36,21.735 C16.2@126.36,26.12 ; 125.984,20.828 124.165,19.009 123.568,19.009 123.381,18.821 122.444,18.821 ; C16.2@126.426,26.146 126.345,26.226 126.345,27.438 cw(c126.738,27.438) 126.738,27.831 133.938,27.831 cw(c133.938,27.332) 134.437,27.332 C10.1@134.437,26.156 ; 127.266,15.678 127.34,15.604 ccw(c127.866,16.13) 127.866,15.386 128.08,15.386 128.095,15.372 J1.7@128.095,14.951 ; C18.2@128.061,7.391 128.107,7.437 J1.8@128.107,9.198 ; J1.11@130.045,9.211 130.059,9.196 130.059,8.409 130.802,7.666 130.908,7.666 131.294,7.28 132.653,7.28 C7.2@132.763,7.391 133.043,7.111 133.177,7.111 133.7,6.588 cw(c132.952,5.841) 134.009,5.841 ; 130.483,8.041 130.68,8.239 130.68,9.196 J1.12@130.695,9.211 ; J1.14@131.995,9.211 131.995,8.556 ccw(c133.153,8.556) C7.2@132.334,7.737 ; C7.2@132.869,7.456 133.083,7.67 133.083,7.679 133.438,8.034 cw(c133.821,7.65) 133.821,8.193 ; 133.821,8.194 134.757,8.194 PS2.4@134.814,8.137 ; 134.012,5.841 134.012,5.034 cw(c133.264,5.034) 133.264,4.287 127.04,4.287 ; U8.5@134.229,22.437 134.373,22.437 134.477,22.541 C9.1@134.477,24.286 ; C9.1@134.461,24.302 C10.1@134.461,26.132 ; 122.444,18.821 122.444,4.774 ccw(c122.93,4.774) 122.93,4.287 127.04,4.287
VLT4_GND: C6.1 C7.1 C8.2 C9.2 C10.2 C11.2 C12.2 C13.1 C14.2 C16.1 C18.1 D6.C J1.4 J1.5 J1.10 PS2.3 R14.1 R17.2 U6.9 U6.15 U7.5 U8.2 U9.2 U10.4 | length 24.3
  Top Layer w0.305: J1.5@129.395,14.951 129.412,14.968 129.412,17.037 v1(129.429,17.055) ; v1(130.032,16.279) 130.038,16.272 130.038,14.957 J1.4@130.045,14.951
  Top Layer w0.381: U6.15@125.464,13.757 125.469,13.752 126.884,13.752 v1(126.889,13.747) ; C18.1@127.997,5.796 128.28,6.08 128.419,6.08 129.355,7.015 129.355,7.176 D6.C@129.39,7.212 ; C18.1@128.044,5.8 C18.1@128.048,5.796 ; J1.10@129.389,9.204 129.389,7.558 D6.C@129.629,7.317 ; v1(130.619,21.453) 130.638,21.471 131.618,21.471 U8.2@131.637,21.49 ; C7.1@132.763,5.811 C7.1@132.895,5.678
  Top Layer w0.508: U10.4@121.05,24.449 121.112,24.449 121.158,24.495 v1@121.158,25.146 ; v1(121.147,16.446) 121.151,16.45 121.151,17.237 C8.2@121.155,17.241 ; v1@123.444,25.146 123.444,24.48 123.49,24.434 U7.5@123.89,24.434 ; C6.1@123.649,17.21 123.663,17.196 123.663,16.382 v1(123.677,16.368) ; C16.1@124.846,26.146 124.862,26.162 124.862,26.956 v1(124.877,26.972) ; U6.9@125.464,6.137 125.529,6.137 125.575,6.091 v1(125.575,5.397) ; C11.2@125.842,18.702 125.996,18.856 125.996,19.562 v1(126.013,19.58) ; C18.1@128.048,5.796 128.073,5.771 128.073,5.001 v1(128.091,4.983) ; C13.1@128.266,18.679 128.272,18.673 128.272,17.708 v1(128.278,17.702) ; v1(129.649,26.972) 129.667,26.954 129.667,26.116 C14.2@129.719,26.064 ; v1(131.245,27.063) 131.249,27.059 131.249,26.15 R17.2@131.254,26.146 ; v1(132.839,4.997) 132.821,5.015 132.821,5.605 C7.1@132.895,5.678 ; C12.2@135.932,20.674 135.941,20.683 135.941,21.531 v1(135.951,21.54) ; C10.2@136.027,26.146 136.031,26.15 136.842,26.15 v1(136.846,26.155) ; C9.2@136.032,24.173 136.035,24.176 136.835,24.176 v1(136.839,24.173) ; v2(137.957,23) 137.957,22.039 R14.1@138.012,21.984
  other v1: 121.168,25.113 123.483,25.15
pads on no net: 1.7 1.8 J1.13 J2.13 J3.13 J4.13 U3.34 U3.A11 U3.A12 U3.A13 U3.A14 U3.A15 U3.A16 U3.A17 U3.A18 U3.A19 U3.A20 U3.A29 U3.A30 U3.A31 U3.A32 U3.A33 U3.A34 U3.A35 U3.A36 U3.A37 U3.A38 U3.A39 U3.A40 U3.B01 U3.B02 U3.B03 U3.B04 U3.B05 U3.B06 U3.B07 U3.B08 U3.B09 U3.B10 U3.B11 U3.B12 U3.B13 U3.B14 U3.B15 U3.B16 U3.B17 U3.B18 U3.B19 U3.B20 U3.B21 U3.B22 U3.B23 U3.B24 U3.B37 U3.B38 U3.B39 U3.B40 U3.C01 U3.C2 U3.C02 U3.C15 U3.C16 U3.C17 U3.C18 U3.C19 U3.C20 U3.C21 U3.C23 U3.C24 U3.C25 U3.C26 U3.C27 U3.C28 U3.C29 U3.C32 U3.C37 U3.C38 U3.C39 U3.C40 U6.6 U6.11 U11.6 U11.11 U20.6 U20.11 U21.6 U21.11 U26.4 U26.5 U26.6 U26.7 U26.10 U26.12 U26.15 U27.4 U27.5 U27.6 U27.7 U27.10 U27.12 U27.15 U28.4 U28.5 U28.6 U28.7 U28.10 U28.12 U28.15 U29.4 U29.5 U29.6 U29.7 U29.10 U29.12 U29.15

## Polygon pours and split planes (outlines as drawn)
VLT1_GND on Bottom Layer "VLT1_GND_L02_P015" (solid, pour order 15): 119.38,104.648 155.702,104.648 155.702,80.264 119.38,80.264
VLT4_GND on Bottom Layer "VLT4_GND_L02_P017" (solid, pour order 17): 119.38,28.448 155.702,28.448 155.702,1.27 119.38,1.27 119.38,3.048
GND_3V3 on Bottom Layer "GND_3V3_L02_P018" (solid, pour order 18): 1.27,104.648 1.778,104.648 118.364,104.648 118.364,1.27 1.27,1.27
SIG_GND on Bottom Layer "SIG_GND_L02_P012" (solid, pour order 12): 58.674,95.25 58.674,76.708 31.242,76.708 31.242,95.25
VLT2_GND on Bottom Layer "VLT2_GND_L02_P016" (solid, pour order 16): 119.38,79.288 155.623,79.288 155.623,54.61 119.38,54.61
VLT3_GND on Bottom Layer "VLT3_GND_L02_P014" (solid, pour order 14): 119.38,52.578 119.38,53.594 155.702,53.594 155.702,29.084 119.38,29.338

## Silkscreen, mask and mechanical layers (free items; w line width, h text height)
Top Overlay:
  text "Q8" at 72.136,103.746 h1.78
  text "Q7" at 77.216,103.746 h1.78
  text "Q6" at 82.296,103.746 h1.78
  text "Q5" at 87.63,103.746 h1.78
  text "Q4" at 92.456,103.746 h1.78
  text "Q3" at 97.536,103.746 h1.78
  text "Q2" at 102.362,103.746 h1.78
  text "Q1" at 107.696,103.746 h1.78
  text "IN1" at 48.768,103.632 h1.78
  text "IN2" at 53.848,103.632 h1.78
  text "IN3" at 58.928,103.652 h1.78
  text "IN4" at 64.262,103.632 h1.78
  text "ADC1" at 1.507,89.154 h1.52 r90
  text "VLT1" at 155.956,88.392 h1.78 r90
  text "EMF Controller 01.08.26" at 63.761,85.714 h2.54
  text "GND1" at 1.507,84.074 h1.52 r90
  text "GND1" at 155.936,83.058 h1.78 r90
  text "Лучшее из двух миров :: energy4all.ru" at 57.912,82.296 h2.54
  text "ADC2" at 1.507,78.994 h1.52 r90
  text "Мищук А.Л." at 70.861,78.586 h2.54
  text "GND2" at 1.507,73.66 h1.52 r90
  text "ADC3" at 1.507,68.834 h1.52 r90
  text "GND3" at 1.507,64.008 h1.52 r90
  text "VLT2" at 156.21,61.214 h1.78 r90
  text "ADC4" at 1.507,58.674 h1.52 r90
  text "GND2" at 156.19,55.88 h1.78 r90
  text "GND4" at 1.507,53.594 h1.52 r90
  text "VLT3" at 156.19,38.354 h1.78 r90
  text "GND3" at 156.25,31.818 h1.78 r90
  text "VLT4" at 156.21,18.034 h1.78 r90
  text "GND4" at 156.19,11.176 h1.78 r90
  text "VCC 9-36" at 34.828,1.521 h1.78
  text "GND" at 30.028,1.41 h1.78
Mechanical 2:
  the board outline again, w0.254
